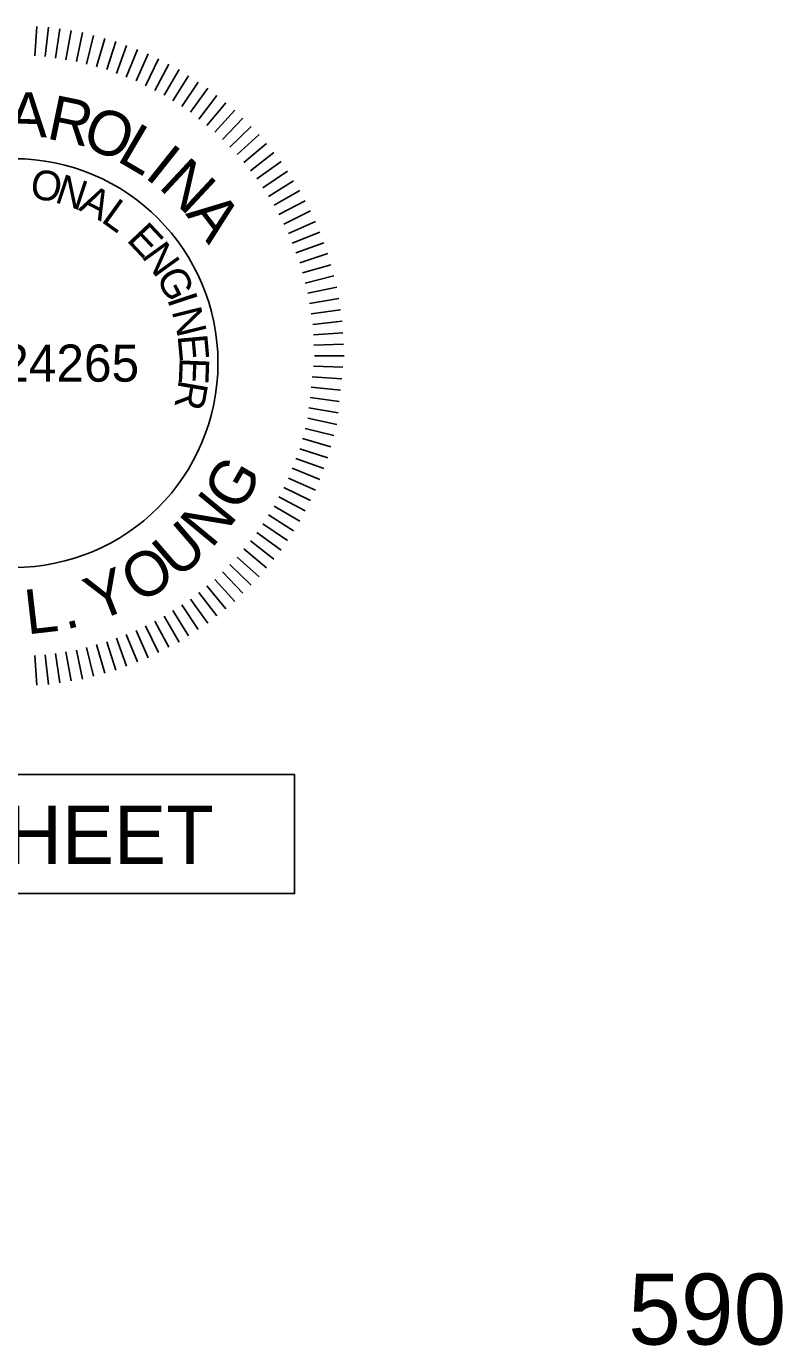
# Model space of a CAD drawing. Extents: x 1964849 to 1967422, y 1116563 to 1122210.
# Drawn here: x 1967331.3 to 1967421.9, y 1119325.5 to 1119483.5 of the extents above; entities that cross this region are included whole.
import ezdxf

# ---------------------------------------------------------------- set-up
doc = ezdxf.new("R2010")
doc.units = 0
for name, color, linetype in [('RD_DDB_Profile_Elev', 7, 'Continuous'), ('RD_Sketch1', 7, 'Continuous'), ('RD_TX_PEShield', 7, 'Continuous')]:
    doc.layers.add(name, color=color, linetype=linetype)

msp = doc.modelspace()

# ---------------------------------------------------------------- linework, layer by layer
at = {"layer": 'RD_Sketch1'}
msp.add_lwpolyline([(1967062.99, 1119393.87), (1967363.41, 1119393.87), (1967363.41, 1119379.61), (1967062.99, 1119379.61)], close=True, dxfattribs=at)
at = {"layer": 'RD_TX_PEShield'}
for p, q in [((1967332.26, 1119479.96), (1967332.51, 1119483.51)), ((1967332.26, 1119479.96), (1967332.51, 1119483.51)), ((1967333.52, 1119479.89), (1967333.89, 1119483.43)), ((1967333.52, 1119479.89), (1967333.89, 1119483.43)), ((1967334.76, 1119479.7), (1967335.26, 1119483.22)), ((1967334.76, 1119479.7), (1967335.26, 1119483.22)), ((1967336, 1119479.5), (1967336.62, 1119483)), ((1967336, 1119479.5), (1967336.62, 1119483)), ((1967337.25, 1119479.3), (1967337.99, 1119482.79)), ((1967337.25, 1119479.3), (1967337.99, 1119482.79)), ((1967337.25, 1119479.3), (1967337.99, 1119482.79)), ((1967338.46, 1119478.98), (1967339.32, 1119482.43)), ((1967338.46, 1119478.98), (1967339.32, 1119482.43)), ((1967338.46, 1119478.98), (1967339.32, 1119482.43)), ((1967339.68, 1119478.65), (1967340.66, 1119482.07)), ((1967339.68, 1119478.65), (1967340.66, 1119482.07)), ((1967339.68, 1119478.65), (1967340.66, 1119482.07)), ((1967340.89, 1119478.33), (1967341.99, 1119481.71)), ((1967340.89, 1119478.33), (1967341.99, 1119481.71)), ((1967340.89, 1119478.33), (1967341.99, 1119481.71)), ((1967342.07, 1119477.88), (1967343.28, 1119481.22)), ((1967342.07, 1119477.88), (1967343.28, 1119481.22)), ((1967342.07, 1119477.88), (1967343.28, 1119481.22)), ((1967343.24, 1119477.43), (1967344.57, 1119480.72)), ((1967343.24, 1119477.43), (1967344.57, 1119480.72)), ((1967343.24, 1119477.43), (1967344.57, 1119480.72)), ((1967344.41, 1119476.97), (1967345.86, 1119480.23)), ((1967344.41, 1119476.97), (1967345.86, 1119480.23)), ((1967344.41, 1119476.97), (1967345.86, 1119480.23)), ((1967345.53, 1119476.4), (1967347.09, 1119479.6)), ((1967345.53, 1119476.4), (1967347.09, 1119479.6)), ((1967345.53, 1119476.4), (1967347.09, 1119479.6)), ((1967346.65, 1119475.83), (1967348.32, 1119478.97)), ((1967346.65, 1119475.83), (1967348.32, 1119478.97)), ((1967346.65, 1119475.83), (1967348.32, 1119478.97)), ((1967347.78, 1119475.26), (1967349.56, 1119478.34)), ((1967347.78, 1119475.26), (1967349.56, 1119478.34)), ((1967347.78, 1119475.26), (1967349.56, 1119478.34)), ((1967348.83, 1119474.58), (1967350.71, 1119477.59)), ((1967348.83, 1119474.58), (1967350.71, 1119477.59)), ((1967348.83, 1119474.58), (1967350.71, 1119477.59)), ((1967349.88, 1119473.89), (1967351.87, 1119476.84)), ((1967349.88, 1119473.89), (1967351.87, 1119476.84)), ((1967349.88, 1119473.89), (1967351.87, 1119476.84)), ((1967350.94, 1119473.21), (1967353.03, 1119476.09)), ((1967350.94, 1119473.21), (1967353.03, 1119476.09)), ((1967350.94, 1119473.21), (1967353.03, 1119476.09)), ((1967351.92, 1119472.41), (1967354.11, 1119475.22)), ((1967351.92, 1119472.41), (1967354.11, 1119475.22)), ((1967351.92, 1119472.41), (1967354.11, 1119475.22)), ((1967352.89, 1119471.62), (1967355.18, 1119474.35)), ((1967352.89, 1119471.62), (1967355.18, 1119474.35)), ((1967352.89, 1119471.62), (1967355.18, 1119474.35)), ((1967353.87, 1119470.83), (1967356.25, 1119473.48)), ((1967353.87, 1119470.83), (1967356.25, 1119473.48)), ((1967353.87, 1119470.83), (1967356.25, 1119473.48)), ((1967354.76, 1119469.94), (1967357.23, 1119472.5)), ((1967354.76, 1119469.94), (1967357.23, 1119472.5)), ((1967354.76, 1119469.94), (1967357.23, 1119472.5)), ((1967355.65, 1119469.05), (1967358.21, 1119471.52)), ((1967355.65, 1119469.05), (1967358.21, 1119471.52)), ((1967355.65, 1119469.05), (1967358.21, 1119471.52)), ((1967356.54, 1119468.16), (1967359.18, 1119470.55)), ((1967356.54, 1119468.16), (1967359.18, 1119470.55)), ((1967356.54, 1119468.16), (1967359.18, 1119470.55)), ((1967357.33, 1119467.19), (1967360.05, 1119469.47)), ((1967357.33, 1119467.19), (1967360.05, 1119469.47)), ((1967357.33, 1119467.19), (1967360.05, 1119469.47)), ((1967358.12, 1119466.21), (1967360.92, 1119468.4)), ((1967358.12, 1119466.21), (1967360.92, 1119468.4)), ((1967358.12, 1119466.21), (1967360.92, 1119468.4)), ((1967358.91, 1119465.23), (1967361.79, 1119467.32)), ((1967358.91, 1119465.23), (1967361.79, 1119467.32)), ((1967358.91, 1119465.23), (1967361.79, 1119467.32)), ((1967359.6, 1119464.18), (1967362.55, 1119466.17)), ((1967359.6, 1119464.18), (1967362.55, 1119466.17)), ((1967359.6, 1119464.18), (1967362.55, 1119466.17)), ((1967360.28, 1119463.12), (1967363.3, 1119465.01)), ((1967360.28, 1119463.12), (1967363.3, 1119465.01)), ((1967360.28, 1119463.12), (1967363.3, 1119465.01)), ((1967360.97, 1119462.07), (1967364.05, 1119463.85)), ((1967360.97, 1119462.07), (1967364.05, 1119463.85)), ((1967360.97, 1119462.07), (1967364.05, 1119463.85)), ((1967361.54, 1119460.95), (1967364.68, 1119462.62)), ((1967361.54, 1119460.95), (1967364.68, 1119462.62)), ((1967361.54, 1119460.95), (1967364.68, 1119462.62)), ((1967362.11, 1119459.83), (1967365.31, 1119461.39)), ((1967362.11, 1119459.83), (1967365.31, 1119461.39)), ((1967362.11, 1119459.83), (1967365.31, 1119461.39)), ((1967362.68, 1119458.71), (1967365.93, 1119460.15)), ((1967362.68, 1119458.71), (1967365.93, 1119460.15)), ((1967362.68, 1119458.71), (1967365.93, 1119460.15)), ((1967363.13, 1119457.53), (1967366.43, 1119458.86)), ((1967363.13, 1119457.53), (1967366.43, 1119458.86)), ((1967363.13, 1119457.53), (1967366.43, 1119458.86)), ((1967363.58, 1119456.36), (1967366.92, 1119457.57)), ((1967363.58, 1119456.36), (1967366.92, 1119457.57)), ((1967363.58, 1119456.36), (1967366.92, 1119457.57)), ((1967364.03, 1119455.18), (1967367.42, 1119456.28)), ((1967364.03, 1119455.18), (1967367.42, 1119456.28)), ((1967364.03, 1119455.18), (1967367.42, 1119456.28)), ((1967364.36, 1119453.97), (1967367.78, 1119454.95)), ((1967364.36, 1119453.97), (1967367.78, 1119454.95)), ((1967364.36, 1119453.97), (1967367.78, 1119454.95)), ((1967364.68, 1119452.76), (1967368.13, 1119453.62)), ((1967364.68, 1119452.76), (1967368.13, 1119453.62)), ((1967364.68, 1119452.76), (1967368.13, 1119453.62)), ((1967365.01, 1119451.54), (1967368.49, 1119452.28)), ((1967365.01, 1119451.54), (1967368.49, 1119452.28)), ((1967365.01, 1119451.54), (1967368.49, 1119452.28)), ((1967365.21, 1119450.3), (1967368.71, 1119450.91)), ((1967365.21, 1119450.3), (1967368.71, 1119450.91)), ((1967365.21, 1119450.3), (1967368.71, 1119450.91)), ((1967365.4, 1119449.06), (1967368.92, 1119449.55)), ((1967365.4, 1119449.06), (1967368.92, 1119449.55)), ((1967365.4, 1119449.06), (1967368.92, 1119449.55)), ((1967365.6, 1119447.81), (1967369.14, 1119448.19)), ((1967365.6, 1119447.81), (1967369.14, 1119448.19)), ((1967365.6, 1119447.81), (1967369.14, 1119448.19)), ((1967365.67, 1119446.56), (1967369.21, 1119446.8)), ((1967365.67, 1119446.56), (1967369.21, 1119446.8)), ((1967365.67, 1119446.56), (1967369.21, 1119446.8)), ((1967365.73, 1119445.3), (1967369.29, 1119445.43)), ((1967365.73, 1119445.3), (1967369.29, 1119445.43)), ((1967365.73, 1119445.3), (1967369.29, 1119445.43)), ((1967365.67, 1119442.79), (1967369.21, 1119442.67)), ((1967365.67, 1119442.79), (1967369.21, 1119442.67)), ((1967365.8, 1119444.05), (1967369.36, 1119444.05)), ((1967365.8, 1119444.05), (1967369.36, 1119444.05)), ((1967365.8, 1119444.05), (1967369.36, 1119444.05)), ((1967365.53, 1119441.54), (1967369.07, 1119441.3)), ((1967365.53, 1119441.54), (1967369.07, 1119441.3)), ((1967365.4, 1119440.3), (1967368.92, 1119439.93)), ((1967365.4, 1119440.3), (1967368.92, 1119439.93)), ((1967365.14, 1119437.81), (1967368.64, 1119437.19)), ((1967365.14, 1119437.81), (1967368.64, 1119437.19)), ((1967365.27, 1119439.05), (1967368.78, 1119438.56)), ((1967365.27, 1119439.05), (1967368.78, 1119438.56)), ((1967365.01, 1119436.55), (1967368.49, 1119435.81)), ((1967365.01, 1119436.55), (1967368.49, 1119435.81)), ((1967364.68, 1119435.34), (1967368.13, 1119434.48)), ((1967364.68, 1119435.34), (1967368.13, 1119434.48)), ((1967364.36, 1119434.12), (1967367.78, 1119433.14)), ((1967364.36, 1119434.12), (1967367.78, 1119433.14)), ((1967363.58, 1119431.73), (1967366.92, 1119430.52)), ((1967363.58, 1119431.73), (1967366.92, 1119430.52)), ((1967364.03, 1119432.91), (1967367.42, 1119431.81)), ((1967364.03, 1119432.91), (1967367.42, 1119431.81)), ((1967363.13, 1119430.56), (1967366.43, 1119429.23)), ((1967363.13, 1119430.56), (1967366.43, 1119429.23)), ((1967362.11, 1119428.26), (1967365.31, 1119426.71)), ((1967362.11, 1119428.26), (1967365.31, 1119426.71)), ((1967362.68, 1119429.38), (1967365.93, 1119427.94)), ((1967362.68, 1119429.38), (1967365.93, 1119427.94)), ((1967361.54, 1119427.14), (1967364.68, 1119425.47)), ((1967361.54, 1119427.14), (1967364.68, 1119425.47)), ((1967360.97, 1119426.02), (1967364.05, 1119424.24)), ((1967360.97, 1119426.02), (1967364.05, 1119424.24)), ((1967359.6, 1119423.91), (1967362.55, 1119421.93)), ((1967359.6, 1119423.91), (1967362.55, 1119421.93)), ((1967360.28, 1119424.97), (1967363.3, 1119423.08)), ((1967360.28, 1119424.97), (1967363.3, 1119423.08)), ((1967358.91, 1119422.86), (1967361.79, 1119420.77)), ((1967358.91, 1119422.86), (1967361.79, 1119420.77)), ((1967357.33, 1119420.9), (1967360.05, 1119418.62)), ((1967357.33, 1119420.9), (1967360.05, 1119418.62)), ((1967358.12, 1119421.88), (1967360.92, 1119419.69)), ((1967358.12, 1119421.88), (1967360.92, 1119419.69)), ((1967355.65, 1119419.04), (1967358.21, 1119416.57)), ((1967355.65, 1119419.04), (1967358.21, 1119416.57)), ((1967356.54, 1119419.93), (1967359.18, 1119417.54)), ((1967356.54, 1119419.93), (1967359.18, 1119417.54)), ((1967353.87, 1119417.26), (1967356.25, 1119414.61)), ((1967354.76, 1119418.15), (1967357.23, 1119415.59)), ((1967354.76, 1119418.15), (1967357.23, 1119415.59)), ((1967351.92, 1119415.68), (1967354.11, 1119412.87)), ((1967351.92, 1119415.68), (1967354.11, 1119412.87)), ((1967352.89, 1119416.47), (1967355.18, 1119413.74)), ((1967352.89, 1119416.47), (1967355.18, 1119413.74)), ((1967349.88, 1119414.2), (1967351.87, 1119411.25)), ((1967349.88, 1119414.2), (1967351.87, 1119411.25)), ((1967350.94, 1119414.88), (1967353.03, 1119412)), ((1967350.94, 1119414.88), (1967353.03, 1119412)), ((1967347.78, 1119412.83), (1967349.56, 1119409.75)), ((1967347.78, 1119412.83), (1967349.56, 1119409.75)), ((1967348.83, 1119413.51), (1967350.71, 1119410.5)), ((1967348.83, 1119413.51), (1967350.71, 1119410.5)), ((1967344.41, 1119411.12), (1967345.86, 1119407.86)), ((1967344.41, 1119411.12), (1967345.86, 1119407.86)), ((1967345.53, 1119411.69), (1967347.09, 1119408.49)), ((1967345.53, 1119411.69), (1967347.09, 1119408.49)), ((1967346.65, 1119412.26), (1967348.32, 1119409.12)), ((1967346.65, 1119412.26), (1967348.32, 1119409.12)), ((1967339.68, 1119409.44), (1967340.66, 1119406.02)), ((1967339.68, 1119409.44), (1967340.66, 1119406.02)), ((1967340.89, 1119409.76), (1967341.99, 1119406.38)), ((1967340.89, 1119409.76), (1967341.99, 1119406.38)), ((1967342.07, 1119410.22), (1967343.28, 1119406.87)), ((1967342.07, 1119410.22), (1967343.28, 1119406.87)), ((1967343.24, 1119410.67), (1967344.57, 1119407.37)), ((1967343.24, 1119410.67), (1967344.57, 1119407.37)), ((1967332.26, 1119408.13), (1967332.51, 1119404.59)), ((1967332.26, 1119408.13), (1967332.51, 1119404.59)), ((1967333.52, 1119408.2), (1967333.89, 1119404.66)), ((1967333.52, 1119408.2), (1967333.89, 1119404.66)), ((1967334.76, 1119408.39), (1967335.26, 1119404.87)), ((1967334.76, 1119408.39), (1967335.26, 1119404.87)), ((1967336, 1119408.59), (1967336.62, 1119405.09)), ((1967336, 1119408.59), (1967336.62, 1119405.09)), ((1967337.25, 1119408.79), (1967337.99, 1119405.31)), ((1967337.25, 1119408.79), (1967337.99, 1119405.31)), ((1967338.46, 1119409.11), (1967339.32, 1119405.66)), ((1967338.46, 1119409.11), (1967339.32, 1119405.66))]:
    msp.add_line(p, q, dxfattribs=at)
msp.add_circle((1967329.75, 1119443.17), 24.48, dxfattribs=at)

# ---------------------------------------------------------------- texts
at = {"layer": 'RD_DDB_Profile_Elev'}
msp.add_text('590', height=8.5, dxfattribs=at).set_placement((1967403.42, 1119325.58))
at = {"layer": 'RD_Sketch1'}
msp.add_text('ALIGNMENT CONTROL CAN BE FOUND ON REFERENCE SHEET', height=7, dxfattribs=at).set_placement((1967066.64, 1119383.16))
at = {"layer": 'RD_TX_PEShield'}
for s, height, rotation, p in [('A', 5.34, 357.9448, (1967328.96, 1119470.36)), ('R', 5.34, 348.267, (1967333.54, 1119470.1)), ('O', 5.34, 339.3286, (1967337.68, 1119469.19)), ('L', 5.34, 329.6507, (1967341.94, 1119467.48)), ('I', 5.34, 321.4663, (1967345.28, 1119465.5)), ('O', 3.56, 350.4045, (1967331.55, 1119462.99)), ('N', 5.34, 317.0007, (1967346.97, 1119464.22)), ('N', 3.56, 341.7029, (1967334.53, 1119462.49)), ('A', 3.56, 333.0013, (1967337.4, 1119461.55)), ('L', 3.56, 324.2997, (1967340.09, 1119460.18)), ('A', 5.34, 307.3229, (1967350.27, 1119461.03)), ('E', 3.56, 313.2251, (1967343.17, 1119457.88)), ('N', 3.56, 305.7317, (1967344.97, 1119456)), ('G', 3.56, 297.0301, (1967346.74, 1119453.55)), ('I', 3.56, 288.3285, (1967348.11, 1119450.86)), ('N', 3.56, 283.8441, (1967348.66, 1119449.4)), ('E', 3.56, 275.1424, (1967349.38, 1119446.47)), ('E', 3.56, 267.6491, (1967349.65, 1119443.88)), ('R', 3.56, 260.1557, (1967349.57, 1119441.28)), ('G', 5.34, 60.1113, (1967356.86, 1119425.14)), ('N', 5.34, 50.4335, (1967353.45, 1119420.84)), ('U', 5.34, 40.7556, (1967349.36, 1119417.18)), ('O', 5.34, 31.0778, (1967344.71, 1119414.25)), ('Y', 5.34, 21.4, (1967339.63, 1119412.15)), ('L', 5.34, 6.5171, (1967331.34, 1119410.65)), ('.', 5.34, 14.7016, (1967335.95, 1119411.21))]:
    msp.add_text(s, height=height, rotation=rotation, dxfattribs=at).set_placement(p)
msp.add_text('NO. 24265', height=4.45, dxfattribs=at).set_placement((1967316, 1119440.94))

doc.saveas('drawing.dxf')
